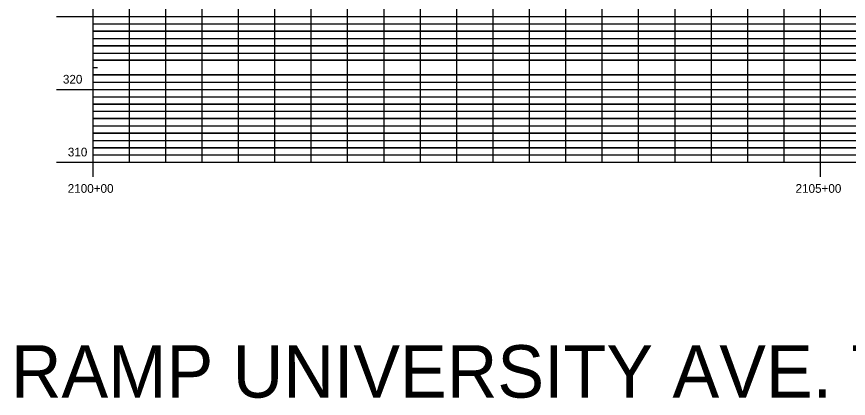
# Model space of a CAD drawing. Extents: x 1195880 to 1289360, y 2059330 to 2086925.
# Drawn here: x 1197010 to 1197582, y 2060533 to 2060795 of the extents above; entities that cross this region are included whole.
import ezdxf

# ---------------------------------------------------------------- set-up
doc = ezdxf.new("R2010")
doc.units = 0
for name, color, linetype in [('51', 7, 'Continuous'), ('Default', 7, 'Continuous'), ('Grid', 7, 'Continuous'), ('Grid Lables', 7, 'Continuous')]:
    doc.layers.add(name, color=color, linetype=linetype)

msp = doc.modelspace()

# ---------------------------------------------------------------- linework, layer by layer
at = {"layer": 'Grid'}
for p, q in [((1197062.41, 2060695.23), (1197062.41, 2061245.23)), ((1197087.41, 2060695.23), (1197087.41, 2061245.23)), ((1197112.41, 2060695.23), (1197112.41, 2061245.23)), ((1197137.41, 2060695.23), (1197137.41, 2061245.23)), ((1197162.41, 2060695.23), (1197162.41, 2061245.23)), ((1197187.41, 2060695.23), (1197187.41, 2061245.23)), ((1197212.41, 2060695.23), (1197212.41, 2061245.23)), ((1197237.41, 2060695.23), (1197237.41, 2061245.23)), ((1197262.41, 2060695.23), (1197262.41, 2061245.23)), ((1197287.41, 2060695.23), (1197287.41, 2061245.23)), ((1197312.41, 2060695.23), (1197312.41, 2061245.23)), ((1197337.41, 2060695.23), (1197337.41, 2061245.23)), ((1197362.41, 2060695.23), (1197362.41, 2061245.23)), ((1197387.41, 2060695.23), (1197387.41, 2061245.23)), ((1197412.41, 2060695.23), (1197412.41, 2061245.23)), ((1197437.41, 2060695.23), (1197437.41, 2061245.23)), ((1197462.41, 2060695.23), (1197462.41, 2061245.23)), ((1197487.41, 2060695.23), (1197487.41, 2061245.23)), ((1197512.41, 2060695.23), (1197512.41, 2061245.23)), ((1197537.41, 2060695.23), (1197537.41, 2061245.23)), ((1197562.41, 2060695.23), (1197562.41, 2061245.23)), ((1197037.41, 2060795.23), (1197062.41, 2060795.23)), ((1197062.41, 2060795.23), (1198062.41, 2060795.23)), ((1197062.41, 2060790.23), (1197065.41, 2060790.23)), ((1197062.41, 2060790.23), (1198062.41, 2060790.23)), ((1197062.41, 2060785.23), (1197065.41, 2060785.23)), ((1197062.41, 2060785.23), (1198062.41, 2060785.23)), ((1198062.41, 2060785.23), (1197062.41, 2060785.23)), ((1197062.41, 2060780.23), (1197065.41, 2060780.23)), ((1197062.41, 2060780.23), (1198062.41, 2060780.23)), ((1197062.41, 2060775.23), (1197065.41, 2060775.23)), ((1197062.41, 2060775.23), (1198062.41, 2060775.23)), ((1198062.41, 2060775.23), (1197062.41, 2060775.23)), ((1197062.41, 2060770.23), (1197065.41, 2060770.23)), ((1197062.41, 2060770.23), (1198062.41, 2060770.23)), ((1197062.41, 2060765.23), (1197065.41, 2060765.23)), ((1197062.41, 2060765.23), (1198062.41, 2060765.23)), ((1198062.41, 2060765.23), (1197062.41, 2060765.23)), ((1197062.41, 2060760.23), (1197065.41, 2060760.23)), ((1197062.41, 2060755.23), (1197065.41, 2060755.23)), ((1197062.41, 2060755.23), (1198062.41, 2060755.23)), ((1198062.41, 2060755.23), (1197062.41, 2060755.23)), ((1197062.41, 2060750.23), (1197065.41, 2060750.23)), ((1197062.41, 2060750.23), (1198062.41, 2060750.23)), ((1197037.41, 2060745.23), (1197062.41, 2060745.23)), ((1197062.41, 2060745.23), (1198062.41, 2060745.23)), ((1197062.41, 2060740.23), (1197065.41, 2060740.23)), ((1197062.41, 2060740.23), (1198062.41, 2060740.23)), ((1197062.41, 2060735.23), (1197065.41, 2060735.23)), ((1197062.41, 2060735.23), (1198062.41, 2060735.23)), ((1198062.41, 2060735.23), (1197062.41, 2060735.23)), ((1197062.41, 2060730.23), (1197065.41, 2060730.23)), ((1197062.41, 2060730.23), (1198062.41, 2060730.23)), ((1197062.41, 2060725.23), (1197065.41, 2060725.23)), ((1197062.41, 2060725.23), (1198062.41, 2060725.23)), ((1198062.41, 2060725.23), (1197062.41, 2060725.23)), ((1197062.41, 2060720.23), (1197065.41, 2060720.23)), ((1197062.41, 2060720.23), (1198062.41, 2060720.23)), ((1197062.41, 2060715.23), (1197065.41, 2060715.23)), ((1197062.41, 2060715.23), (1198062.41, 2060715.23)), ((1198062.41, 2060715.23), (1197062.41, 2060715.23)), ((1197062.41, 2060710.23), (1197065.41, 2060710.23)), ((1197062.41, 2060710.23), (1198062.41, 2060710.23)), ((1197062.41, 2060705.23), (1197065.41, 2060705.23)), ((1197062.41, 2060705.23), (1198062.41, 2060705.23)), ((1198062.41, 2060705.23), (1197062.41, 2060705.23)), ((1197062.41, 2060700.23), (1197065.41, 2060700.23)), ((1197062.41, 2060700.23), (1198062.41, 2060700.23)), ((1197037.41, 2060695.23), (1197062.41, 2060695.23)), ((1197062.41, 2060695.23), (1198062.41, 2060695.23)), ((1197062.41, 2060685.23), (1197062.41, 2060695.23)), ((1197087.41, 2060695.23), (1197087.41, 2060698.23)), ((1197112.41, 2060695.23), (1197112.41, 2060698.23)), ((1197137.41, 2060695.23), (1197137.41, 2060698.23)), ((1197162.41, 2060695.23), (1197162.41, 2060698.23)), ((1197187.41, 2060695.23), (1197187.41, 2060698.23)), ((1197212.41, 2060695.23), (1197212.41, 2060698.23)), ((1197237.41, 2060695.23), (1197237.41, 2060698.23)), ((1197262.41, 2060695.23), (1197262.41, 2060698.23)), ((1197287.41, 2060695.23), (1197287.41, 2060698.23)), ((1197312.41, 2060695.23), (1197312.41, 2060698.23)), ((1197337.41, 2060695.23), (1197337.41, 2060698.23)), ((1197362.41, 2060695.23), (1197362.41, 2060698.23)), ((1197387.41, 2060695.23), (1197387.41, 2060698.23)), ((1197412.41, 2060695.23), (1197412.41, 2060698.23)), ((1197437.41, 2060695.23), (1197437.41, 2060698.23)), ((1197462.41, 2060695.23), (1197462.41, 2060698.23)), ((1197487.41, 2060695.23), (1197487.41, 2060698.23)), ((1197512.41, 2060695.23), (1197512.41, 2060698.23)), ((1197537.41, 2060695.23), (1197537.41, 2060698.23)), ((1197562.41, 2060685.23), (1197562.41, 2060695.23))]:
    msp.add_line(p, q, dxfattribs=at)

# ---------------------------------------------------------------- texts
at = {"layer": '51'}
msp.add_text('-', height=0.0001, dxfattribs=at).set_placement((1197062.41, 2060695.23))
at = {"layer": 'Default'}
msp.add_text('RAMP UNIVERSITY AVE. TO WB I-630', height=36, rotation=360, dxfattribs=at).set_placement((1197005.97, 2060533.58))
at = {"layer": 'Grid Lables'}
for s, p in [('320', (1197041.72, 2060749.23)), ('310', (1197045.12, 2060699.23)), ('2100+00', (1197045.05, 2060674.23)), ('2105+00', (1197545.28, 2060674.23))]:
    msp.add_text(s, height=6, dxfattribs=at).set_placement(p)

doc.saveas('drawing.dxf')
